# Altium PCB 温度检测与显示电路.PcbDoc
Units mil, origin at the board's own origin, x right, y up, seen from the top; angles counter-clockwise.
Board outline 6000 x 4000 mil, 2 copper layers (Top Layer, Bottom Layer); 17 components, 20 nets, 100 pads, 8 vias.
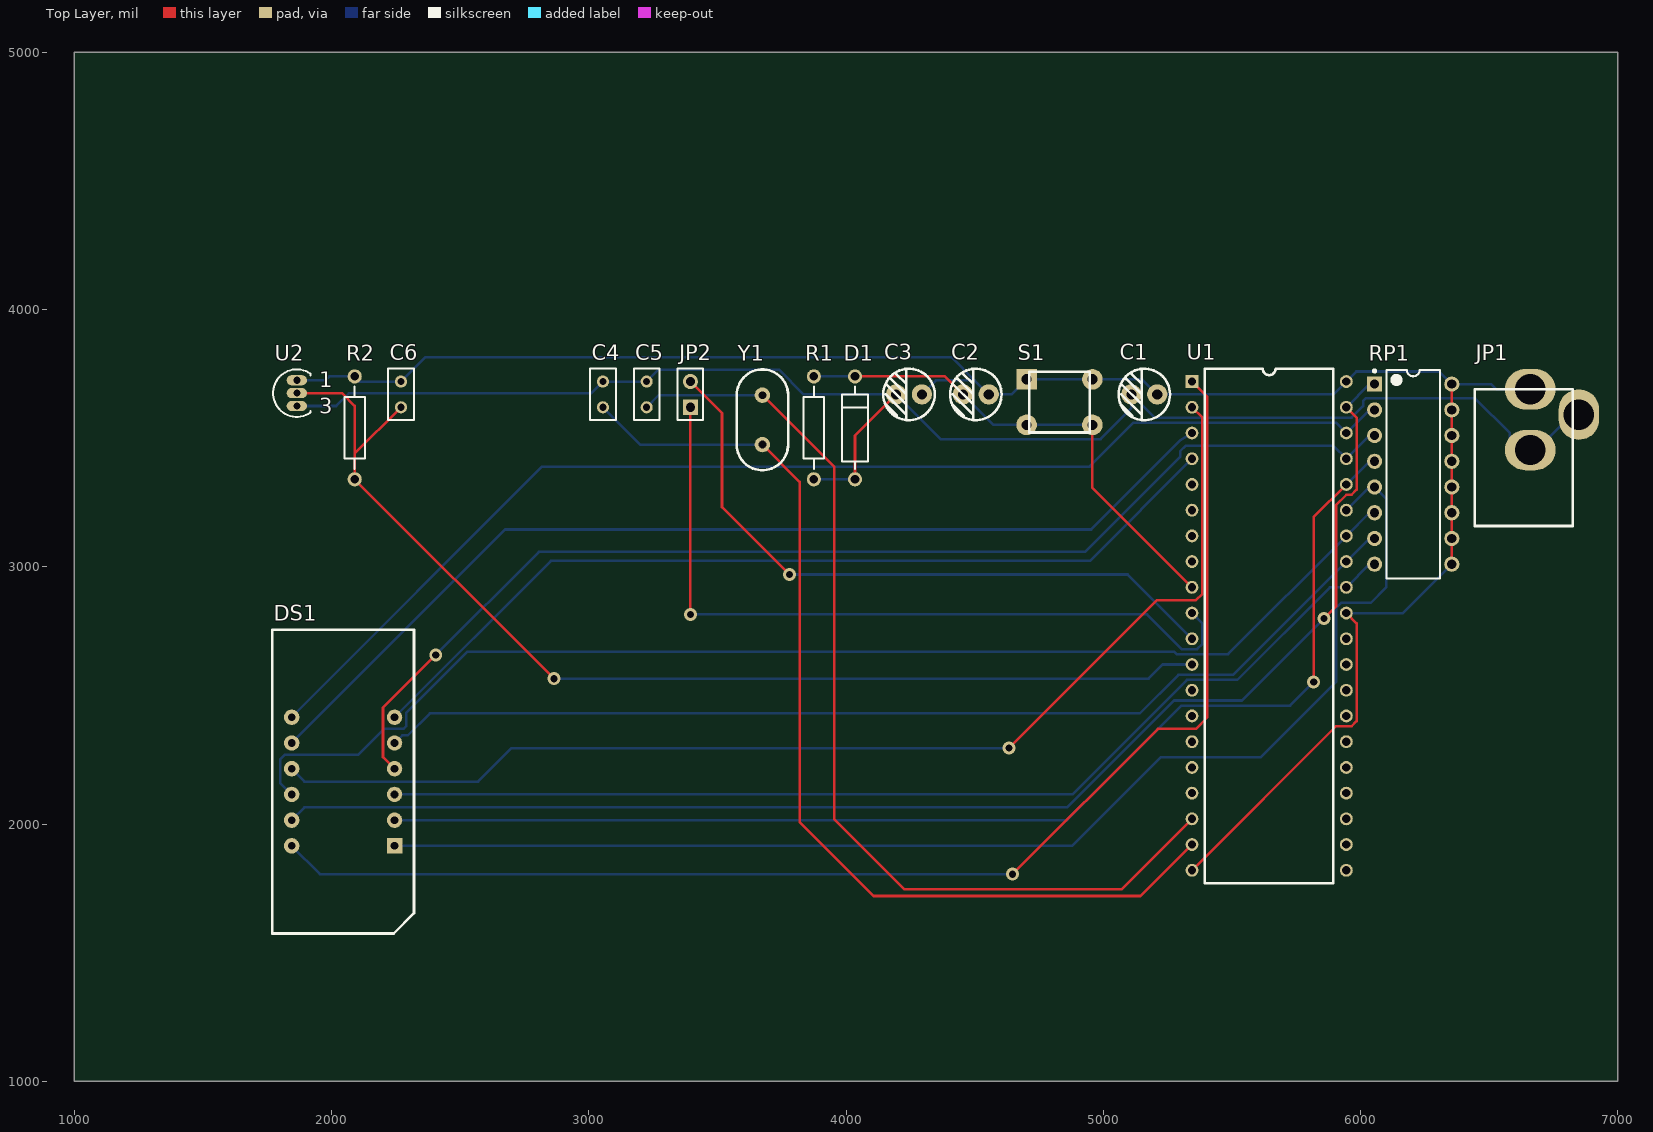
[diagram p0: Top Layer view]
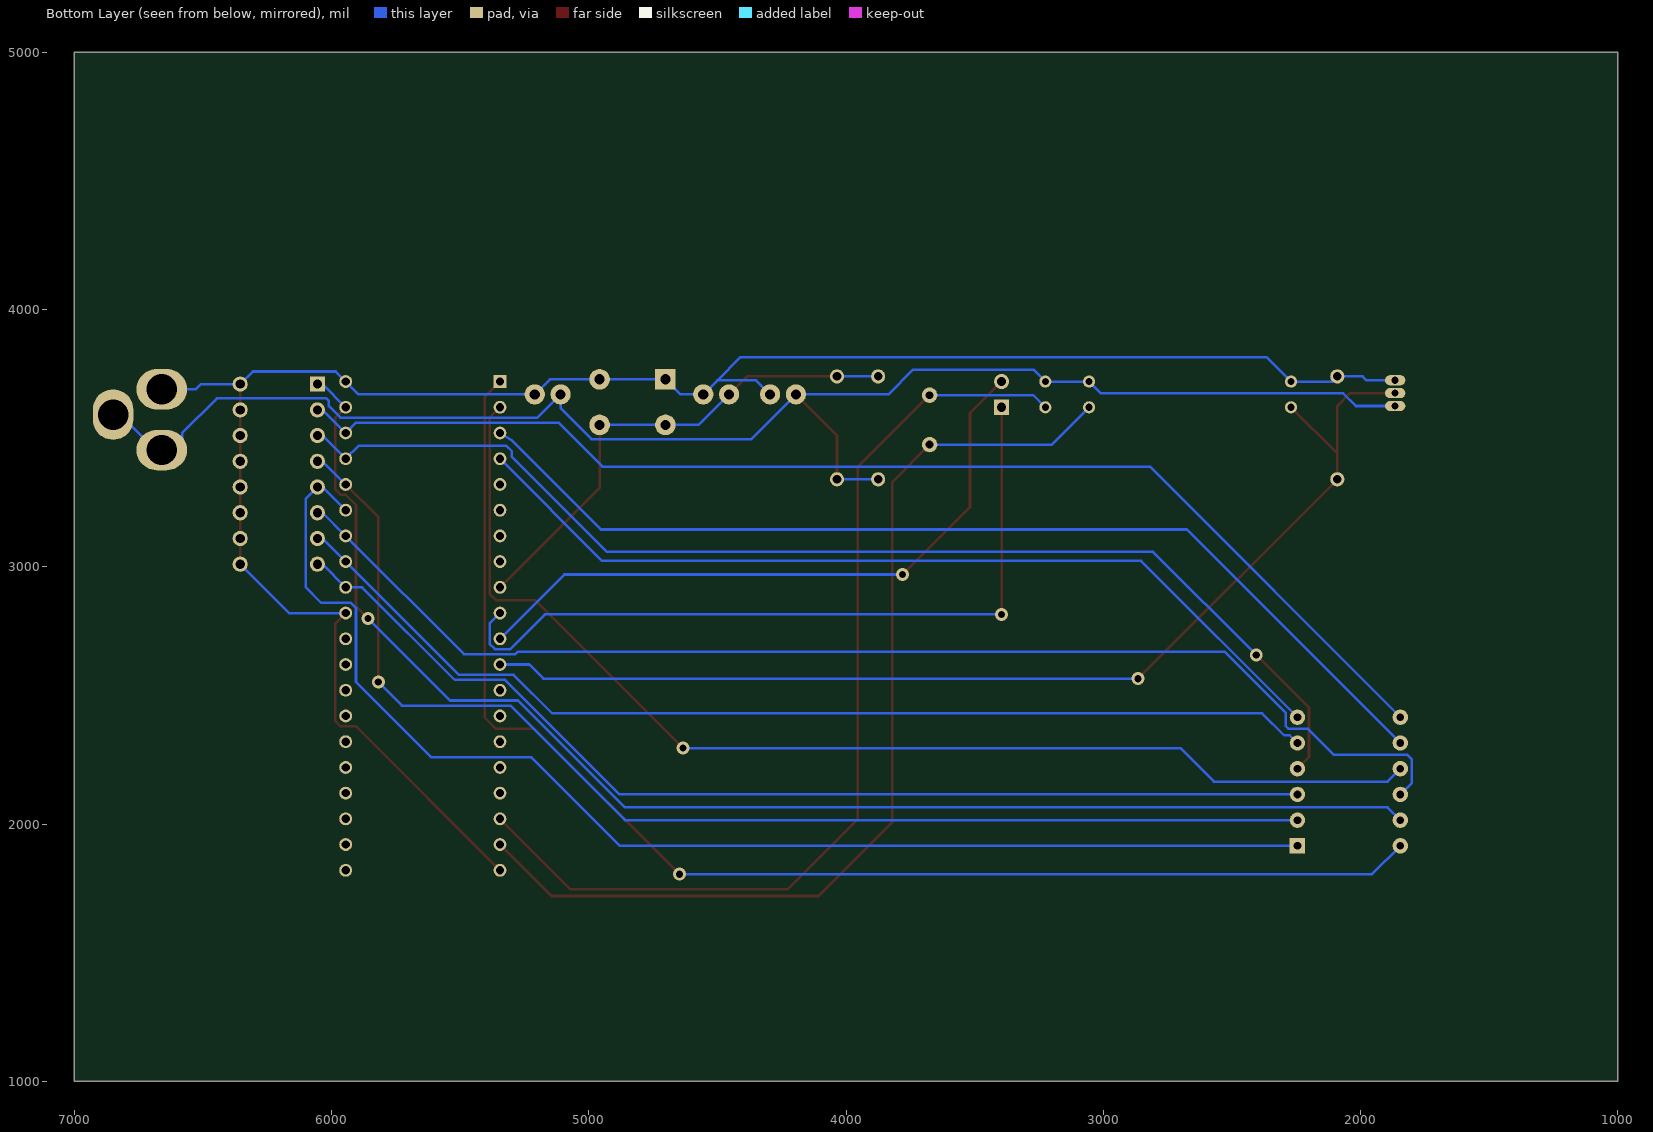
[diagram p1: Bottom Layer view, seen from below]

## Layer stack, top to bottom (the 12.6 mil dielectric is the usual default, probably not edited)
Top Solder: solder mask 0.4, Solder Resist, Dk 3.5
Top Layer: signal copper 1.4
Dielectric 1: dielectric 12.6, FR-4, Dk 4.8
Bottom Layer: signal copper 1.4
Bottom Solder: solder mask 0.4, Solder Resist, Dk 3.5

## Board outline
1000,1000 7000,1000 7000,5000 1000,5000

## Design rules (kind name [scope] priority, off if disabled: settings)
Clearance [All] p1: gap=10
PolygonConnect [All] p1: connectstyle=Relief reliefconductorwidth=10 reliefentries=4 polygonreliefangle="90 Angle" airgapwidth=10
RoutingVias [All] p1: holewidth=28 width=50 viastyle="Through Hole" minholewidth=28 minwidth=50 maxholewidth=28 maxwidth=50
SolderMaskExpansion [All] p1: expansion=4
Width [All] p1: maxlimit=10 minlimit=10 preferedwidth=10
30 further rules are at their usual default settings.

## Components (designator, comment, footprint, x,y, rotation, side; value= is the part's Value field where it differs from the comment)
C1 "10UF" "RB.1/.2 - ZJM" 5210,3670 r0 top
C2 "10uF" "rb.1/.2 - ZJM" 4555,3670 r0 top
C3 "10UF" "RB.1/.2 - ZJM" 4295,3670 r0 top
C4 "33pF" rad-0.1 3055,3670 r90 top
C5 "33pF" rad-0.1 3225,3670 r90 top
C6 "104" RAD-0.1 2270,3670 r90 top
D1 "DIODE" DIODE-0.4 4035,3540 r90 top
DS1 "DPY_7-SEG_DP_1" DPY_7SEG_DP_4bit 2045,2165 r90 top
JP1 "DC-JACK" DC-JACK 6660,3690 r90 top
JP2 "4PIN/2.5" HDR1X2 3395,3620 r90 top
R1 "10Kohm" AXIAL-0.4 3875,3540 r90 top
R2 "4.7K" AXIAL-0.4 2090,3540 r90 top
RP1 "10Kohm*8" DIP-16 6205,3360 r0 top
S1 "KEY" KEY4.5*6.5 4830,3640 r0 top
U1 "STC89C51" STC89C51 5345,3720 r0 top
U2 "DS18B20" TO-92 1865,3675 r0 top
Y1 "11.0592M" XTAL11.0592M 3675,3475 r90 top

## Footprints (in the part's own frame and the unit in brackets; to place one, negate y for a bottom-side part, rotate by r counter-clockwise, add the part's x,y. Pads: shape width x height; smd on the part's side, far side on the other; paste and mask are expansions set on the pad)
AXIAL-0.4 [mm] "Axial Device, Thru-Hole; 2 Leads; 0.4 in Pin Spacing"
  round 1.4 hole 0.85: 1(-5.08,0) 2(5.08,0)
  silkscreen extent -4.06,-1.02 4.06,1.02
DC-JACK [mm]
  oval 4x5 hole 3: 1(0,0) 2(-6,0)
  oval 5x4 hole 3: 3(-2.5,-4.8)
  silkscreen extent -13.5,-4.2 0,5.5
DIODE-0.4 [mm] "Diode, Thru-Hole; 2 Leads; 0.4 in Pin Spacing"
  round 1.4 hole 0.85: 1(-5.08,0) 2(5.08,0)
  silkscreen extent -4.06,-1.27 4.06,1.27
DIP-16 [mm] "DIP; 16 Leads; Row Spacing 7.62 mm; Pitch 2.54 mm"
  rect 1.5x1.5 hole 0.9: 1(-3.81,8.89)
  round 1.5 hole 0.9: 2(-3.81,6.35) 3(-3.81,3.81) 4(-3.81,1.27) 5(-3.81,-1.27) 6(-3.81,-3.81) 7(-3.81,-6.35) 8(-3.81,-8.89) 9(3.81,-8.89) 10(3.81,-6.35) 11(3.81,-3.81) 12(3.81,-1.27) 13(3.81,1.27) 14(3.81,3.81) 15(3.81,6.35) 16(3.81,8.89)
  silkscreen extent -3.93,-10.3 2.65,10.31, body extent -3.6,-10.28 3.6,10.28, height 5.08
DPY_7SEG_DP_4bit [mil]
  rect 60x60 hole 30: 1(-250,-200)
  round 60 hole 30: 2(-150,-200) 3(-50,-200) 4(50,-200) 5(150,-200) 6(250,-200) 7(250,200) 8(150,200) 9(50,200) 10(-50,200) 11(-150,200) 12(-250,200)
  silkscreen extent -591,-276 591,276
HDR1X2 [mm] "Connector; Header; 2 Position"
  rect 1.5x1.5 hole 0.9: 1(0,0)
  round 1.5 hole 0.9: 2(2.54,0)
  silkscreen extent -1.27,-1.27 3.81,1.27
KEY4.5*6.5 [mil]
  rect 80x80 hole 40: 1(-127.95,88.58)
  round 80 hole 40: 1(127.95,88.58) 2(-127.95,-88.58) 2(127.95,-88.58)
  silkscreen extent -118,-118 118,118
rad-0.1 [mm] "Radial Cap, Thru-Hole; 2 Leads; 0.1 in Pin Spacing"
  round 1.2 hole 0.7: 1(-1.27,0) 2(1.27,0)
  silkscreen extent -2.54,-1.27 2.54,1.27
RAD-0.1 [mm] "Radial Cap, Thru-Hole; 2 Leads; 0.1 in Pin Spacing"
  round 1.2 hole 0.7: 1(-1.27,0) 2(1.27,0)
  silkscreen extent -2.54,-1.27 2.54,1.27
"RB.1/.2 - ZJM" [mm]
  round 2 hole 1: 1(0,0) 2(-2.55,0)
  silkscreen extent -3.82,-2.54 1.26,2.54
"rb.1/.2 - ZJM" [mm]
  round 2 hole 1: 1(0,0) 2(-2.55,0)
  silkscreen extent -3.82,-2.54 1.26,2.54
STC89C51 [mil]
  rect 50x50 hole 32: 1(0,0)
  round 50 hole 32: 2(0,-100) 3(0,-200) 4(0,-300) 5(0,-400) 6(0,-500) 7(0,-600) 8(0,-700) 9(0,-800) 10(0,-900) 11(0,-1000) 12(0,-1100) 13(0,-1200) 14(0,-1300) 15(0,-1400) 16(0,-1500) 17(0,-1600) 18(0,-1700) 19(0,-1800) 20(0,-1900) 21(600,-1900) 22(600,-1800) 23(600,-1700) 24(600,-1600) 25(600,-1500) 26(600,-1400) 27(600,-1300) 28(600,-1200) 29(600,-1100) 30(600,-1000) 31(600,-900) 32(600,-800) 33(600,-700) 34(600,-600) 35(600,-500) 36(600,-400) 37(600,-300) 38(600,-200) 39(600,-100) 40(600,0)
  silkscreen extent 50,-1950 550,50
TO-92 [mm] "TO, Flat Index; 3 In-Line, Axial Leads; Body Dia. 4.6mm; Leads 0.41 x 0.39 mm (max)"
  oval 2x1 hole 0.7: 1(0,1.27) 2(0,0) 3(0,-1.27)
  silkscreen extent -2.34,-2.34 1.35,2.34
XTAL11.0592M [mil]
  round 60 hole 30: 1(0,0) 2(192,0)
  silkscreen extent -100,-100 292,100

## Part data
C1 C3: library part ELECTRO1, "Electrolytic Capacitor"
C2: library part "CAPACITOR POL", "Capacitor"
C4 C5 C6: library part CAP, "Capacitor"
D1: "Diode"
DS1: "Seven-Segment Display, Right Hand Decimal"
JP2: library part "4 HEADER", "4 Pin Header"
R1 R2: library part RES1
RP1: library part RESPACK3
S1: library part SW-PB
Y1: library part CRYSTAL, "Crystal"

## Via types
v1: diameter 50, hole 28, Top Layer to Bottom Layer, 8 vias

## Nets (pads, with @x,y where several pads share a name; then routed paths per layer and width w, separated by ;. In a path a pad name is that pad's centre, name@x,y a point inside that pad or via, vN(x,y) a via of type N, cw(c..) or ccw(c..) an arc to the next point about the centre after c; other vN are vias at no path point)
GND: C1.2 C3.2 C4.2 C5.2 D1.1 JP1.2 JP1.3 R1.1 U2.3 | length 6072.6
  Top Layer w10: D1.1 4035,3510.39 C3.2
  Bottom Layer w10: U2.3 2018,3625 2067,3674 3009,3674 C4.2 C5.2 3271,3766 3739,3766 3835,3670 C3.2 4368.19,3496.42 4989.42,3496.42 5109.61,3616.61 C1.2 5199.61,3580 5965,3580 6010,3625 6010,3645 6020,3655 6446,3655 6581,3520 6581,3453.78 JP1.2 6685,3453.78 6822.79,3591.57 JP1.3 ; R1.1 D1.1
NetC4_1: C4.1 U1.19 Y1.1 | length 3934.8
  Top Layer w10: Y1.1 3820,3330 3820,2007 4107,1720 5145,1720 U1.19
  Bottom Layer w10: C4.1 3200,3475 Y1.1
NetC5_1: C5.1 U1.18 Y1.2 | length 3850.6
  Top Layer w10: Y1.2 3955,3387 3955,2018 4227,1746 5071,1746 U1.18
  Bottom Layer w10: C5.1 3272,3667 Y1.2
P0.0: DS1.11 RP1.1 U1.39 | length 5386.9
  Top Layer w10: v1(5858,2799) 5905,2846 5905,3240 5945,3280 5965,3280 5985,3300 5985,3580 U1.39
  Bottom Layer w10: DS1.11 1895,2065 4860,2065 5275,2480 5539,2480 v1(5858,2799) ; U1.39 6035,3710 RP1.1
P0.1: DS1.7 RP1.2 U1.38 | length 4738.1
  Bottom Layer w10: DS1.7 2819,3389 4946.5,3389 5117.5,3560 5905,3560 U1.38 6035,3610 RP1.2
P0.2: DS1.4 RP1.3 U1.37 | length 4603.2
  Top Layer w10: DS1.4 2200,2260 2200,2452 v1(2405,2657)
  Bottom Layer w10: v1(2405,2657) 2806,3058 4930,3058 5299,3427 5299,3449 5320,3470 5895,3470 U1.37 6035,3510 RP1.3
P0.3: DS1.2 RP1.4 U1.36 | length 4763.3
  Top Layer w10: v1(5818,2552) 5818,3193 U1.36
  Bottom Layer w10: DS1.2 4860,2015 5305,2460 5726,2460 v1(5818,2552) ; U1.36 6035,3410 RP1.4
P0.4: DS1.1 RP1.5 U1.35 | length 4995.7
  Bottom Layer w10: DS1.1 4879,1915 5224,2260 5612.59,2260 5905,2552.41 5905,2840 5925,2860 6040,2860 6100,2920 6100,3265 RP1.5 6035,3310 U1.35
P0.5: DS1.10 RP1.6 U1.34 | length 4844.4
  Bottom Layer w10: DS1.10 1800,2160 1800,2250 1820,2270 2104,2270 2204,2370 2280,2370 2290,2380 2290,2431 2529,2670 5275,2670 5285,2660 5485,2660 U1.34 6035,3210 RP1.6
P0.6: DS1.5 RP1.7 U1.33 | length 4139.3
  Bottom Layer w10: DS1.5 2275,2345 2297.03,2345 2382.03,2430 5142,2430 5292,2580 5505,2580 U1.33 6035,3110 RP1.7
P0.7: DS1.3 RP1.8 U1.32 | length 4180.7
  Bottom Layer w10: DS1.3 4880,2115 5325,2560 5521.03,2560 5881.03,2920 U1.32 6035,3010 RP1.8
P3.2_SENSOR: C6.1 R2.1 U1.12 U2.2 | length 4384.1
  Top Layer w10: U2.2 2040,3675 2090,3625 2090,3440 ; C6.1 2090,3440 ; v1(2865,2565) R2.1 2090,3440
  Bottom Layer w10: v1(2865,2565) 5176,2565 5231,2620 U1.12
P10: DS1.12 U1.1 | length 5188.1
  Top Layer w10: v1(4647,1805) 5212,2370 5360,2370 5405,2415 5405,3660 U1.1
  Bottom Layer w10: DS1.12 1955,1805 v1(4647,1805)
P11: DS1.9 U1.2 | length 4604.7
  Top Layer w10: v1(4634,2295) 5209,2870 5360,2870 5385,2895 5385,3580 U1.2
  Bottom Layer w10: DS1.9 1895,2165 2570,2165 2700,2295 v1(4634,2295)
P12: DS1.8 U1.3 | length 3995.5
  Bottom Layer w10: DS1.8 2675,3145 4953.05,3145 5300,3491.95 U1.3
P13: DS1.6 U1.4 | length 3516.3
  Bottom Layer w10: DS1.6 2853,3023 4948,3023 U1.4
RESET: C2.2 D1.2 R1.2 S1.2 U1.9 | length 1952.8
  Top Layer w10: D1.2 4384.61,3740 C2.2 ; S1.2@4957.95,3551.42 4957.95,3307.05 U1.9
  Bottom Layer w10: R1.2 D1.2 ; C2.2 4573.19,3551.42 4702.05,3551.42 S1.2@4957.95,3551.42
RXD: JP2.1 U1.10 | length 2995.8
  Top Layer w10: v1(3395,2815) JP2.1
  Bottom Layer w10: v1(3395,2815) 5170,2815 5305,2680 5365,2680 5385,2700 5385,2780 U1.10
TXD: JP2.2 U1.11 | length 2578
  Top Layer w10: JP2.2 3518,3597 3518,3232 v1(3780,2970)
  Bottom Layer w10: v1(3780,2970) 5095,2970 U1.11
VDD: C1.1 C2.1 C3.1 C6.2 JP1.1 R2.2 RP1.9 RP1.10 RP1.11 RP1.12 RP1.13 RP1.14 RP1.15 RP1.16 S1.1 U1.20 U1.31 U1.40 U2.1 | length 7756.2
  Top Layer w10: U1.20 5905,2380 5965,2380 5985,2400 5985,2780 U1.31 ; RP1.9 RP1.10 RP1.11 RP1.12 RP1.13 RP1.14 RP1.15 RP1.16
  Bottom Layer w10: U2.1 1977,3725 1992,3740 R2.2 2110,3720 C6.2 2365,3815 4410,3815 4500,3725 ; C3.1 4350,3725 4500,3725 ; U1.31 6165,2820 RP1.9 ; JP1.1 6528,3690 6508,3710 RP1.16 6306,3759 5984,3759 U1.40 5895,3670 C1.1 5151.42,3728.58 4957.95,3728.58 4702.05,3728.58 4643.47,3670 C2.1 4500,3725
pads on no net: U1.5 U1.6 U1.7 U1.8 U1.13 U1.14 U1.15 U1.16 U1.17 U1.21 U1.22 U1.23 U1.24 U1.25 U1.26 U1.27 U1.28 U1.29 U1.30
